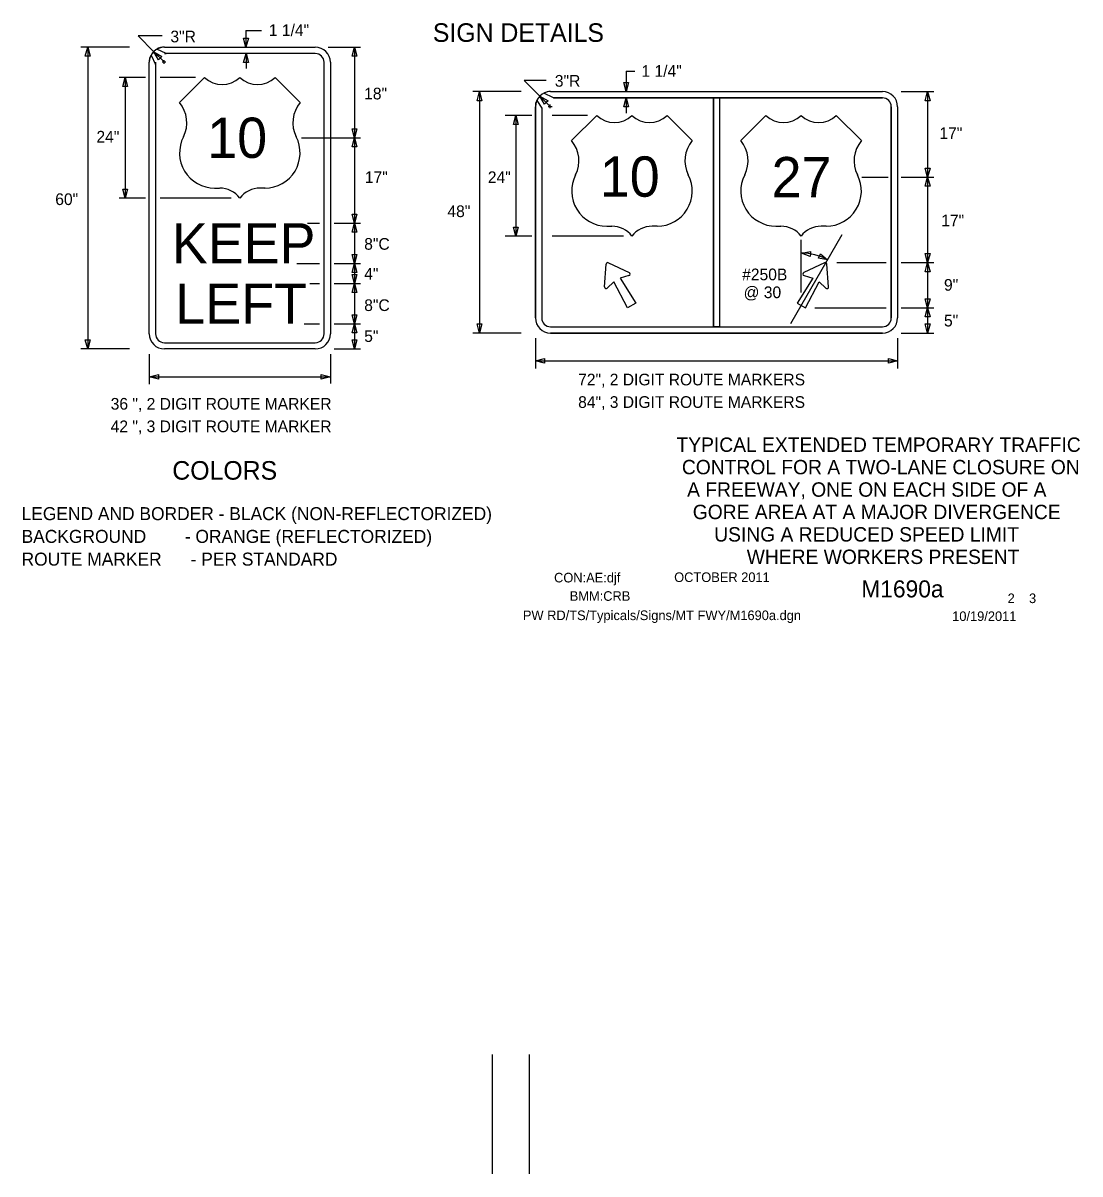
# Model space of a CAD drawing. Extents: x 16486 to 19506, y 5576 to 7023.
# Drawn here: x 17777 to 18460, y 5576 to 6320 of the extents above; entities that cross this region are included whole.
import ezdxf

# ---------------------------------------------------------------- set-up
doc = ezdxf.new("R2010")
doc.units = 0
for name, color, linetype in [('ALI_LEGAL_EX', 7, 'Continuous'), ('BORDER', 7, 'Continuous'), ('BORDER_SIGNAL_WO', 7, 'Continuous'), ('TRAFFIC_SIGNS_PR', 7, 'Continuous'), ('TYPICAL_EX', 7, 'Continuous'), ('TYPICAL_TEXT_DIMEN_PR', 7, 'Continuous')]:
    doc.layers.add(name, color=color, linetype=linetype)

msp = doc.modelspace()

# ---------------------------------------------------------------- linework, layer by layer
at = {"layer": 'ALI_LEGAL_EX'}
for p, q in [((18079.61, 5652.91), (18079.61, 5575.75)), ((18103.61, 5652.91), (18103.61, 5575.75))]:
    msp.add_line(p, q, dxfattribs=at)
at = {"layer": 'TRAFFIC_SIGNS_PR'}
for p, q in [((17860.3, 6300.32), (17859.29, 6298.82)), ((17869.08, 6299.88), (17862.99, 6302.62)), ((17867.88, 6303.94), (17965.38, 6303.94)), ((17858.13, 6118.69), (17858.13, 6294.19)), ((17859.32, 6298.74), (17862.19, 6292.7)), ((17862.19, 6294.19), (17862.19, 6118.69)), ((17965.38, 6299.88), (17867.88, 6299.88)), ((17971.06, 6118.69), (17971.06, 6294.19)), ((17975.13, 6294.19), (17975.13, 6118.69)), ((18119.35, 6271.19), (18113.12, 6274.21)), ((18117.4, 6275.24), (18331.9, 6275.24)), ((18117.4, 6275.24), (18331.9, 6275.24)), ((18119.34, 6271.18), (18222.62, 6271.18)), ((18331.9, 6271.18), (18119.34, 6271.18)), ((18222.62, 6271.18), (18222.62, 6123.31)), ((18226.68, 6271.18), (18226.68, 6123.31)), ((18226.68, 6271.18), (18331.9, 6271.18)), ((18107.65, 6265.49), (18107.65, 6128.99)), ((18107.65, 6128.99), (18107.65, 6265.49)), ((18108.57, 6269.5), (18111.71, 6264.46)), ((18111.71, 6264.44), (18111.71, 6128.99)), ((18111.71, 6264.44), (18111.71, 6128.99)), ((18337.59, 6265.49), (18337.59, 6219.74)), ((18337.59, 6128.99), (18337.59, 6265.49)), ((18341.65, 6265.49), (18341.65, 6128.99)), ((18341.65, 6265.49), (18341.65, 6128.99)), ((18337.59, 6219.74), (18337.59, 6128.99)), ((18152.25, 6149.1), (18153.4, 6163.82)), ((18154.91, 6164.69), (18168.23, 6158.33)), ((18294.38, 6164.69), (18281.07, 6158.33)), ((18297.05, 6149.1), (18295.9, 6163.82)), ((18117.4, 6123.31), (18331.9, 6123.31)), ((18117.4, 6119.24), (18331.9, 6119.24)), ((18331.9, 6119.24), (18117.4, 6119.24)), ((17867.88, 6113), (17965.38, 6113)), ((17965.38, 6108.94), (17867.88, 6108.94))]:
    msp.add_line(p, q, dxfattribs=at)
for points in [[(18119.34, 6271.18), (18119.32, 6271.19)], [(18111.71, 6264.46), (18111.71, 6264.44)], [(18168.07, 6156.36), (18162.34, 6154.78), (18172.56, 6138.61), (18167.16, 6135.49), (18158.27, 6152.43), (18154.04, 6148.26)], [(18281.23, 6156.36), (18286.96, 6154.78), (18276.74, 6138.61), (18282.14, 6135.49), (18291.03, 6152.43), (18295.26, 6148.26)]]:
    msp.add_lwpolyline(points, dxfattribs=at)
msp.add_lwpolyline([(18222.62, 6271.18), (18226.68, 6271.18), (18226.68, 6123.31), (18222.62, 6123.31)], close=True, dxfattribs=at)
for centre, radius, start, end in [((17867.88, 6294.19), 9.75, 90, 180), ((17867.29, 6296.37), 7.6, 85.58319, 124.53531), ((17965.38, 6294.19), 9.75, 0, 90), ((17865.16, 6294.78), 7.06, 145.86811, 184.82317), ((17856.73, 6293.45), 5.51, 352.24294, 7.75653), ((17868.48, 6304.31), 4.47, 262.2432, 277.7568), ((17965.38, 6294.19), 5.69, 0, 90), ((18117.4, 6265.49), 9.75, 90, 180), ((18117.4, 6265.49), 9.75, 90, 180), ((18116.72, 6268.68), 6.6, 84.11162, 123.06374), ((18118.34, 6278.36), 7.24, 277.81035, 278.05403), ((18331.9, 6265.49), 9.75, 0, 90), ((18331.9, 6265.49), 9.75, 0, 90), ((18331.9, 6265.49), 5.69, 0, 89.99421), ((18331.9, 6265.49), 5.69, 0, 90), ((18113.78, 6266.2), 6.17, 147.60925, 186.56283), ((18154.46, 6163.73), 1.06, 64.48226, 175.51774), ((18294.84, 6163.73), 1.06, 4.48226, 115.51774), ((18167.77, 6157.38), 1.06, 285.9885, 64.48226), ((18281.53, 6157.38), 1.06, 115.51774, 254.0115), ((18153.31, 6149.02), 1.06, 175.51775, 314.01151), ((18295.99, 6149.02), 1.06, 225.98849, 4.48225), ((18117.4, 6128.99), 9.75, 180, 270), ((18117.4, 6128.99), 9.75, 180, 270), ((18117.4, 6128.99), 5.69, 180, 270), ((18117.4, 6128.99), 5.69, 180, 270), ((18331.9, 6128.99), 9.75, 270, 0), ((18331.9, 6128.99), 5.69, 270, 0), ((18331.9, 6128.99), 9.75, 270, 0), ((18331.9, 6128.99), 5.69, 270, 0), ((17867.88, 6118.69), 9.75, 180, 270), ((17867.88, 6118.69), 5.69, 180, 270), ((17965.38, 6118.69), 5.69, 270, 0), ((17965.38, 6118.69), 9.75, 270, 0)]:
    msp.add_arc(centre, radius, start, end, dxfattribs=at)
at = {"layer": 'TYPICAL_EX'}
for p, q in [((17877.63, 6268.19), (17893.88, 6284.44)), ((17955.63, 6268.19), (17939.38, 6284.44)), ((18131.01, 6243.58), (18147.26, 6259.83)), ((18209.01, 6243.58), (18192.76, 6259.83)), ((18240.29, 6243.58), (18256.54, 6259.83)), ((18318.29, 6243.58), (18302.04, 6259.83)), ((17900.35, 6212.9), (17903.6, 6212.9)), ((17932.9, 6212.9), (17929.65, 6212.9)), ((18153.74, 6188.29), (18156.99, 6188.29)), ((18186.28, 6188.29), (18183.03, 6188.29)), ((18263.01, 6188.29), (18266.26, 6188.29)), ((18295.56, 6188.29), (18292.31, 6188.29))]:
    msp.add_line(p, q, dxfattribs=at)
for centre, radius, start, end in [((17905.25, 6296.28), 16.42, 226.14041, 313.85958), ((17928, 6296.28), 16.42, 226.14042, 313.85959), ((17862.23, 6255.18), 20.16, 333.09768, 40.19361), ((17971.03, 6255.18), 20.16, 139.80639, 206.90233), ((18158.64, 6271.67), 16.42, 226.14041, 313.85958), ((18181.39, 6271.67), 16.42, 226.14042, 313.85959), ((18267.91, 6271.67), 16.42, 226.14041, 313.85958), ((18290.66, 6271.67), 16.42, 226.14042, 313.85959), ((17900.4, 6235.63), 22.73, 152.6698, 269.90132), ((17932.86, 6235.63), 22.73, 270.09868, 27.3302), ((18115.61, 6230.57), 20.16, 333.09768, 40.19361), ((18224.41, 6230.57), 20.16, 139.80639, 206.90233), ((18224.89, 6230.57), 20.16, 333.09768, 40.19361), ((18333.69, 6230.57), 20.16, 139.80639, 206.90233), ((18153.78, 6211.02), 22.73, 152.6698, 269.90132), ((18186.24, 6211.02), 22.73, 270.09868, 27.3302), ((18263.06, 6211.02), 22.73, 152.6698, 269.90132), ((18295.52, 6211.02), 22.73, 270.09868, 27.3302), ((17903.65, 6196.62), 16.28, 37.1038, 90.13853), ((17929.61, 6196.62), 16.28, 89.86147, 142.8962), ((18157.03, 6172.01), 16.28, 37.1038, 90.13853), ((18182.99, 6172.01), 16.28, 89.86147, 142.8962), ((18266.31, 6172.01), 16.28, 37.1038, 90.13853), ((18292.27, 6172.01), 16.28, 89.86147, 142.8962)]:
    msp.add_arc(centre, radius, start, end, dxfattribs=at)
at = {"layer": 'TYPICAL_TEXT_DIMEN_PR'}
for p, q in [((17866.5, 6311.23), (17850.84, 6311.23)), ((17850.84, 6311.23), (17861.08, 6300.99)), ((17920.6, 6303.94), (17919.03, 6309.8)), ((17919.03, 6309.8), (17920.6, 6309.8)), ((17920.6, 6314.7), (17920.6, 6303.94)), ((17920.6, 6314.7), (17930.71, 6314.7)), ((17920.6, 6309.8), (17922.17, 6309.8)), ((17922.17, 6309.8), (17920.6, 6303.94)), ((17845.3, 6303.94), (17814, 6303.94)), ((17816.77, 6298.08), (17818.34, 6303.94)), ((17818.34, 6303.94), (17818.34, 6108.94)), ((17818.34, 6303.94), (17819.91, 6298.08)), ((17861.08, 6300.99), (17867.64, 6294.43)), ((17864.11, 6295.73), (17861.08, 6300.99)), ((17861.08, 6300.99), (17866.33, 6297.95)), ((17973.67, 6303.94), (17994.63, 6303.94)), ((17989.16, 6298.08), (17990.73, 6303.94)), ((17990.73, 6303.94), (17990.73, 6245.44)), ((17990.73, 6303.94), (17992.3, 6298.08)), ((17818.34, 6298.08), (17816.77, 6298.08)), ((17819.91, 6298.08), (17818.34, 6298.08)), ((17865.22, 6296.84), (17864.11, 6295.73)), ((17866.33, 6297.95), (17865.22, 6296.84)), ((17866.43, 6294.43), (17868.85, 6294.43)), ((17867.64, 6293.22), (17867.64, 6295.64)), ((17919.08, 6294.02), (17920.65, 6299.88)), ((17920.65, 6294.02), (17919.08, 6294.02)), ((17920.65, 6299.88), (17920.65, 6290.13)), ((17920.65, 6299.88), (17922.22, 6294.02)), ((17922.22, 6294.02), (17920.65, 6294.02)), ((17990.73, 6298.08), (17989.16, 6298.08)), ((17992.3, 6298.08), (17990.73, 6298.08)), ((18166.26, 6288.4), (18166.26, 6275.24)), ((18166.26, 6288.4), (18171.78, 6288.4)), ((17855.76, 6284.44), (17838.63, 6284.44)), ((17840.95, 6278.58), (17842.52, 6284.44)), ((17842.52, 6278.58), (17840.95, 6278.58)), ((17842.52, 6284.44), (17842.52, 6206.44)), ((17842.52, 6284.44), (17844.1, 6278.58)), ((17844.1, 6278.58), (17842.52, 6278.58)), ((17887.99, 6284.44), (17865.12, 6284.44)), ((18114.54, 6282.53), (18100.36, 6282.53)), ((18100.36, 6282.53), (18110.51, 6272.38)), ((18166.26, 6275.24), (18164.69, 6281.11)), ((18164.69, 6281.11), (18166.26, 6281.11)), ((18166.26, 6281.11), (18167.83, 6281.11)), ((18167.83, 6281.11), (18166.26, 6275.24)), ((18098.42, 6275.24), (18067.12, 6275.24)), ((18069.89, 6269.38), (18071.46, 6275.24)), ((18071.46, 6275.24), (18071.46, 6119.24)), ((18071.46, 6275.24), (18073.03, 6269.38)), ((18110.51, 6272.38), (18117.16, 6265.73)), ((18113.55, 6267.12), (18110.51, 6272.38)), ((18110.51, 6272.38), (18115.77, 6269.35)), ((18164.74, 6265.32), (18166.31, 6271.18)), ((18164.74, 6265.32), (18166.31, 6271.18)), ((18166.31, 6271.18), (18166.31, 6261.43)), ((18166.31, 6271.18), (18167.88, 6265.32)), ((18166.31, 6271.18), (18167.88, 6265.32)), ((18344.02, 6275.24), (18364.98, 6275.24)), ((18359.51, 6269.38), (18361.08, 6275.24)), ((18361.08, 6275.24), (18361.08, 6219.99)), ((18361.08, 6275.24), (18362.66, 6269.38)), ((18071.46, 6269.38), (18069.89, 6269.38)), ((18073.03, 6269.38), (18071.46, 6269.38)), ((18114.66, 6268.23), (18113.55, 6267.12)), ((18115.77, 6269.35), (18114.66, 6268.23)), ((18115.95, 6265.73), (18118.37, 6265.73)), ((18117.16, 6264.53), (18117.16, 6266.94)), ((18166.31, 6265.32), (18164.74, 6265.32)), ((18166.31, 6265.32), (18164.74, 6265.32)), ((18167.88, 6265.32), (18166.31, 6265.32)), ((18167.88, 6265.32), (18166.31, 6265.32)), ((18361.08, 6269.38), (18359.51, 6269.38)), ((18362.66, 6269.38), (18361.08, 6269.38)), ((18105.28, 6259.83), (18088.15, 6259.83)), ((18093.45, 6253.97), (18095.02, 6259.83)), ((18095.02, 6259.83), (18095.02, 6181.83)), ((18095.02, 6259.83), (18096.59, 6253.97)), ((18141.38, 6259.83), (18118.5, 6259.83)), ((17990.73, 6245.44), (17989.16, 6251.3)), ((17989.16, 6251.3), (17990.73, 6251.3)), ((17990.73, 6251.3), (17992.3, 6251.3)), ((17992.3, 6251.3), (17990.73, 6245.44)), ((18095.02, 6253.97), (18093.45, 6253.97)), ((18096.59, 6253.97), (18095.02, 6253.97)), ((17956.52, 6245.44), (17994.63, 6245.44)), ((17989.16, 6239.58), (17990.73, 6245.44)), ((17990.73, 6245.44), (17990.73, 6190.19)), ((17990.73, 6245.44), (17992.3, 6239.58)), ((17990.73, 6239.58), (17989.16, 6239.58)), ((17992.3, 6239.58), (17990.73, 6239.58)), ((18318.46, 6219.99), (18335.62, 6219.99)), ((18344.02, 6219.99), (18364.98, 6219.99)), ((18361.08, 6219.99), (18359.51, 6225.86)), ((18359.51, 6225.86), (18361.08, 6225.86)), ((18359.51, 6214.13), (18361.08, 6219.99)), ((18361.08, 6225.86), (18362.66, 6225.86)), ((18362.66, 6225.86), (18361.08, 6219.99)), ((18361.08, 6219.99), (18361.08, 6164.74)), ((18361.08, 6219.99), (18362.66, 6214.13)), ((17842.52, 6206.44), (17840.95, 6212.3)), ((17840.95, 6212.3), (17842.52, 6212.3)), ((17842.52, 6212.3), (17844.1, 6212.3)), ((17844.1, 6212.3), (17842.52, 6206.44)), ((18361.08, 6214.13), (18359.51, 6214.13)), ((18362.66, 6214.13), (18361.08, 6214.13)), ((17855.76, 6206.44), (17838.63, 6206.44)), ((17911.12, 6206.44), (17865.12, 6206.44)), ((17960.46, 6190.19), (17968.14, 6190.19)), ((17977.5, 6190.19), (17994.63, 6190.19)), ((17990.73, 6190.19), (17989.16, 6196.05)), ((17989.16, 6196.05), (17990.73, 6196.05)), ((17989.16, 6184.33), (17990.73, 6190.19)), ((17990.73, 6196.05), (17992.3, 6196.05)), ((17992.3, 6196.05), (17990.73, 6190.19)), ((17990.73, 6190.19), (17990.73, 6164.19)), ((17990.73, 6190.19), (17992.3, 6184.33)), ((17990.73, 6184.33), (17989.16, 6184.33)), ((17992.3, 6184.33), (17990.73, 6184.33)), ((18105.28, 6181.83), (18088.15, 6181.83)), ((18095.02, 6181.83), (18093.45, 6187.69)), ((18093.45, 6187.69), (18095.02, 6187.69)), ((18095.02, 6187.69), (18096.59, 6187.69)), ((18096.59, 6187.69), (18095.02, 6181.83)), ((18164.5, 6181.83), (18118.5, 6181.83)), ((18272.68, 6125.34), (18305.92, 6182.93)), ((18279.44, 6145.5), (18279.44, 6179.49)), ((17990.73, 6164.19), (17989.16, 6170.05)), ((17989.16, 6170.05), (17990.73, 6170.05)), ((17990.73, 6170.05), (17992.3, 6170.05)), ((17992.3, 6170.05), (17990.73, 6164.19)), ((18279.47, 6170.94), (18285.46, 6171.9)), ((18285.14, 6168.77), (18279.47, 6170.94)), ((18285.3, 6170.33), (18285.14, 6168.77)), ((18285.46, 6171.9), (18285.3, 6170.33)), ((18290.45, 6167.61), (18291.14, 6169.03)), ((18296.42, 6166.48), (18290.45, 6167.61)), ((18291.14, 6169.03), (18291.82, 6170.44)), ((18291.82, 6170.44), (18296.42, 6166.48)), ((18361.08, 6164.74), (18359.51, 6170.61)), ((18359.51, 6170.61), (18361.08, 6170.61)), ((18361.08, 6170.61), (18362.66, 6170.61)), ((18362.66, 6170.61), (18361.08, 6164.74)), ((17953.44, 6164.19), (17968.14, 6164.19)), ((17977.5, 6164.19), (17994.63, 6164.19)), ((17989.16, 6158.33), (17990.73, 6164.19)), ((17990.73, 6164.19), (17990.73, 6151.19)), ((17990.73, 6164.19), (17992.3, 6158.33)), ((18302.39, 6164.74), (18334.26, 6164.74)), ((18344.02, 6164.74), (18364.98, 6164.74)), ((18359.51, 6158.88), (18361.08, 6164.74)), ((18361.08, 6164.74), (18361.08, 6135.49)), ((18361.08, 6164.74), (18362.66, 6158.88)), ((17990.73, 6158.33), (17989.16, 6158.33)), ((17990.73, 6151.19), (17989.16, 6157.05)), ((17989.16, 6157.05), (17990.73, 6157.05)), ((17992.3, 6158.33), (17990.73, 6158.33)), ((17990.73, 6157.05), (17992.3, 6157.05)), ((17992.3, 6157.05), (17990.73, 6151.19)), ((18361.08, 6158.88), (18359.51, 6158.88)), ((18362.66, 6158.88), (18361.08, 6158.88)), ((17961.79, 6151.19), (17968.14, 6151.19)), ((17977.5, 6151.19), (17994.63, 6151.19)), ((17989.16, 6145.33), (17990.73, 6151.19)), ((17990.73, 6145.33), (17989.16, 6145.33)), ((17990.73, 6151.19), (17990.73, 6125.19)), ((17990.73, 6151.19), (17992.3, 6145.33)), ((17992.3, 6145.33), (17990.73, 6145.33)), ((18361.08, 6135.49), (18359.51, 6141.36)), ((18359.51, 6141.36), (18361.08, 6141.36)), ((18361.08, 6141.36), (18362.66, 6141.36)), ((18362.66, 6141.36), (18361.08, 6135.49)), ((17990.73, 6125.19), (17989.16, 6131.05)), ((17989.16, 6131.05), (17990.73, 6131.05)), ((17990.73, 6131.05), (17992.3, 6131.05)), ((17992.3, 6131.05), (17990.73, 6125.19)), ((18288.26, 6135.49), (18334.26, 6135.49)), ((18344.02, 6135.49), (18364.98, 6135.49)), ((18359.51, 6129.63), (18361.08, 6135.49)), ((18361.08, 6129.63), (18359.51, 6129.63)), ((18361.08, 6135.49), (18361.08, 6119.24)), ((18361.08, 6135.49), (18362.66, 6129.63)), ((18362.66, 6129.63), (18361.08, 6129.63)), ((17958.29, 6125.19), (17968.14, 6125.19)), ((17977.5, 6125.19), (17994.63, 6125.19)), ((17989.16, 6119.33), (17990.73, 6125.19)), ((17990.73, 6125.19), (17990.73, 6108.94)), ((17990.73, 6125.19), (17992.3, 6119.33)), ((18071.46, 6119.24), (18069.89, 6125.11)), ((18069.89, 6125.11), (18071.46, 6125.11)), ((18071.46, 6125.11), (18073.03, 6125.11)), ((18073.03, 6125.11), (18071.46, 6119.24)), ((18361.08, 6119.24), (18359.51, 6125.11)), ((18359.51, 6125.11), (18361.08, 6125.11)), ((18361.08, 6125.11), (18362.66, 6125.11)), ((18362.66, 6125.11), (18361.08, 6119.24)), ((17818.34, 6108.94), (17816.77, 6114.8)), ((17816.77, 6114.8), (17818.34, 6114.8)), ((17818.34, 6114.8), (17819.91, 6114.8)), ((17819.91, 6114.8), (17818.34, 6108.94)), ((17990.73, 6119.33), (17989.16, 6119.33)), ((17990.73, 6108.94), (17989.16, 6114.8)), ((17989.16, 6114.8), (17990.73, 6114.8)), ((17992.3, 6119.33), (17990.73, 6119.33)), ((17990.73, 6114.8), (17992.3, 6114.8)), ((17992.3, 6114.8), (17990.73, 6108.94)), ((18098.42, 6119.24), (18067.12, 6119.24)), ((18107.65, 6115.9), (18107.65, 6096.34)), ((18341.65, 6115.9), (18341.65, 6096.34)), ((18344.02, 6119.24), (18361.15, 6119.24)), ((18344.02, 6119.24), (18364.98, 6119.24)), ((18344.02, 6119.24), (18361.15, 6119.24)), ((17845.3, 6108.94), (17814, 6108.94)), ((17977.5, 6108.94), (17994.63, 6108.94)), ((17858.13, 6105.6), (17858.13, 6086.24)), ((17975.13, 6105.6), (17975.13, 6086.7)), ((18107.65, 6101.27), (18113.51, 6102.84)), ((18107.65, 6101.27), (18341.65, 6101.27)), ((18113.51, 6099.7), (18107.65, 6101.27)), ((18113.51, 6102.84), (18113.51, 6101.27)), ((18113.51, 6101.27), (18113.51, 6099.7)), ((18335.79, 6101.27), (18335.79, 6102.84)), ((18335.79, 6102.84), (18341.65, 6101.27)), ((18341.65, 6101.27), (18335.79, 6099.7)), ((18335.79, 6099.7), (18335.79, 6101.27)), ((17858.13, 6090.97), (17863.99, 6092.54)), ((17863.99, 6092.54), (17863.99, 6090.97)), ((17969.27, 6090.97), (17969.27, 6092.54)), ((17969.27, 6092.54), (17975.13, 6090.97)), ((17858.13, 6090.97), (17975.13, 6090.97)), ((17863.99, 6089.4), (17858.13, 6090.97)), ((17863.99, 6090.97), (17863.99, 6089.4)), ((17975.13, 6090.97), (17969.27, 6089.4)), ((17969.27, 6089.4), (17969.27, 6090.97))]:
    msp.add_line(p, q, dxfattribs=at)
msp.add_arc((18279.63, 6136.5), 34.39, 60.74521, 90.32117, dxfattribs=at)

# ---------------------------------------------------------------- texts
at = {"layer": 'BORDER'}
for s, p in [('TYPICAL EXTENDED TEMPORARY TRAFFIC', (18198.79, 6042.44)), ('CONTROL FOR A TWO-LANE CLOSURE ON', (18202.29, 6027.95)), ('A FREEWAY, ONE ON EACH SIDE OF A', (18205.66, 6013.45)), ('GORE AREA AT A MAJOR DIVERGENCE', (18209.3, 5998.96)), ('USING A REDUCED SPEED LIMIT', (18223.16, 5984.47)), ('WHERE WORKERS PRESENT', (18244.16, 5969.97))]:
    msp.add_text(s, height=9.3, dxfattribs=at).set_placement(p)
at = {"layer": 'BORDER_SIGNAL_WO'}
for s, height, p in [('CON:AE:djf  ', 6.2, (18119.69, 5958.06)), ('    OCTOBER 2011    ', 6.2, (18188.08, 5958.34)), ('    M1690a   ', 11, (18301.86, 5948.38)), ('BMM:CRB   ', 6.2, (18129.81, 5946.17)), (' 2    3 ', 6.2, (18410.45, 5944.7)), ('PW RD/TS/Typicals/Signs/MT FWY/M1690a.dgn      ', 6.2, (18099.55, 5933.71)), ('10/19/2011    ', 6.2, (18376.93, 5933.13))]:
    msp.add_text(s, height=height, dxfattribs=at).set_placement(p)
at = {"layer": 'TRAFFIC_SIGNS_PR'}
for s, p in [('10', (17895.6, 6232.44)), ('10', (18149.25, 6207.37)), ('27', (18260.26, 6207.01)), ('KEEP', (17872.73, 6164.19)), ('LEFT', (17874.97, 6125.19))]:
    msp.add_text(s, height=26, dxfattribs=at).set_placement(p)
at = {"layer": 'TYPICAL_TEXT_DIMEN_PR'}
for s, height, p in [('1 1/4"', 7.55, (17935.4, 6311.2)), ('SIGN DETAILS', 12, (18041.35, 6307.41)), ('3"R', 7.55, (17871.77, 6307.1)), ('3"R', 7.55, (18120.18, 6278.45)), ('1 1/4"', 7.55, (18176.18, 6284.82)), ('18"', 7.55, (17996.97, 6270.21)), ('24"', 7.55, (17823.97, 6242.33)), ('17"', 7.55, (18368.66, 6244.6)), ('17"', 7.55, (17997.43, 6216.16)), ('24"', 7.55, (18076.88, 6216.16)), ('60"', 7.55, (17797.37, 6201.96)), ('48"', 7.55, (18050.76, 6194.14)), ('17"', 7.55, (18369.86, 6188.24)), ('8"C', 7.55, (17997, 6173.05)), ('4" ', 7.55, (17997, 6153.79)), ('#250B', 7.55, (18241.21, 6153.34)), ('9"', 7.55, (18371.64, 6146.59)), ('@ 30', 7.55, (18242.15, 6141.78)), ('8"C', 7.55, (17997, 6133.46)), ('5"', 7.55, (18371.64, 6123.49)), ('5" ', 7.55, (17997, 6113.49)), ('72", 2 DIGIT ROUTE MARKERS', 7.55, (18135.23, 6085.41)), ('36 ", 2 DIGIT ROUTE MARKER', 7.55, (17833.18, 6069.71)), ('84", 3 DIGIT ROUTE MARKERS', 7.55, (18135.23, 6070.86)), ('42 ", 3 DIGIT ROUTE MARKER', 7.55, (17833.18, 6055.16)), ('COLORS', 12, (17873, 6024.47)), ('LEGEND AND BORDER - BLACK (NON-REFLECTORIZED)', 8.4, (17775.62, 5998.31)), ('BACKGROUND        - ORANGE (REFLECTORIZED)', 8.4, (17775.62, 5983.61)), ('ROUTE MARKER      - PER STANDARD', 8.4, (17775.62, 5968.91))]:
    msp.add_text(s, height=height, dxfattribs=at).set_placement(p)

doc.saveas('drawing.dxf')
